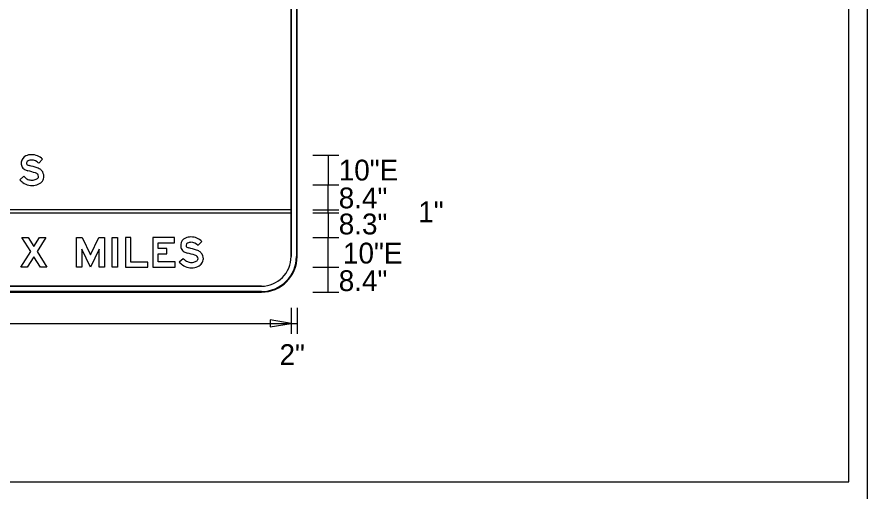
# Model space of a CAD drawing. Extents: x 17890484 to 17890754, y 17897495 to 17897992.
# Drawn here: x 17890540.84 to 17890564.64, y 17897572.31 to 17897585.59 of the extents above; entities that cross this region are included whole.
import ezdxf

# ---------------------------------------------------------------- set-up
doc = ezdxf.new("R2010")
doc.units = 0
for name, color, linetype in [('GSBWFill', 7, 'Continuous'), ('GSColorFill', 7, 'Continuous'), ('GSDims', 7, 'Continuous'), ('GSOutline', 7, 'Continuous'), ('SheetLinesMisc2_dp', 7, 'Continuous')]:
    doc.layers.add(name, color=color, linetype=linetype)

msp = doc.modelspace()

# ---------------------------------------------------------------- linework, layer by layer
at = {"layer": 'GSBWFill'}
for p, q in [((17890548.517, 17897590.883), (17890548.517, 17897578.883)), ((17890548.683, 17897578.883), (17890548.683, 17897590.883)), ((17890548.517, 17897580.186), (17890528.85, 17897580.186)), ((17890528.85, 17897580.103), (17890548.517, 17897580.103)), ((17890548.517, 17897580.103), (17890548.517, 17897580.186)), ((17890547.683, 17897578.049), (17890529.685, 17897578.049)), ((17890529.685, 17897577.883), (17890547.683, 17897577.883))]:
    msp.add_line(p, q, dxfattribs=at)
for points in [[(17890541.555, 17897581.605), (17890541.448, 17897581.5)], [(17890540.918, 17897581.034), (17890541.032, 17897581.132)], [(17890546.021, 17897579.3), (17890545.913, 17897579.195)], [(17890545.384, 17897578.729), (17890545.497, 17897578.827)]]:
    msp.add_lwpolyline(points, dxfattribs=at)
for points in [[(17890541.498, 17897578.582), (17890541.313, 17897578.877), (17890541.128, 17897578.582), (17890540.951, 17897578.582), (17890541.224, 17897579.018), (17890540.976, 17897579.415), (17890541.153, 17897579.415), (17890541.313, 17897579.159), (17890541.473, 17897579.415), (17890541.651, 17897579.415), (17890541.402, 17897579.018), (17890541.676, 17897578.582)], [(17890542.901, 17897578.931), (17890543.131, 17897579.415), (17890543.292, 17897579.415), (17890543.292, 17897578.582), (17890543.142, 17897578.582), (17890543.142, 17897579.09), (17890542.901, 17897578.582), (17890542.659, 17897579.09), (17890542.659, 17897578.582), (17890542.509, 17897578.582), (17890542.509, 17897579.415), (17890542.67, 17897579.415)], [(17890543.509, 17897578.582), (17890543.509, 17897579.415), (17890543.659, 17897579.415), (17890543.659, 17897578.582)], [(17890544.501, 17897578.582), (17890544.501, 17897578.727), (17890544.026, 17897578.727), (17890544.026, 17897579.415), (17890543.876, 17897579.415), (17890543.876, 17897578.582)], [(17890545.267, 17897578.732), (17890544.792, 17897578.732), (17890544.792, 17897578.956), (17890545.038, 17897578.956), (17890545.038, 17897579.106), (17890544.792, 17897579.106), (17890544.792, 17897579.265), (17890545.255, 17897579.265), (17890545.255, 17897579.415), (17890544.642, 17897579.415), (17890544.642, 17897578.582), (17890545.267, 17897578.582)]]:
    msp.add_lwpolyline(points, close=True, dxfattribs=at)
for centre, radius, start, end in [((17890541.176, 17897581.501), 0.218, 113.3248, 174.1421), ((17890541.247, 17897581.336), 0.398, 90, 113.3248), ((17890541.176, 17897581.501), 0.0679, 113.3248, 174.1421), ((17890541.247, 17897581.336), 0.248, 90, 113.3248), ((17890541.247, 17897581.303), 0.431, 44.4342, 90), ((17890541.247, 17897581.303), 0.281, 44.4342, 90), ((17890541.196, 17897581.499), 0.238, 174.1421, 201.2247), ((17890541.148, 17897581.481), 0.186, 201.2247, 240.1812), ((17890541.234, 17897581.631), 0.359, 240.1812, 256.1067), ((17890541.196, 17897581.499), 0.0882, 174.1421, 201.2247), ((17890541.148, 17897581.481), 0.0363, 201.2247, 240.1812), ((17890541.234, 17897581.631), 0.209, 240.1812, 256.1067), ((17890540.212, 17897577.501), 4.045, 72.8961, 76.1067), ((17890541.284, 17897580.985), 0.4, 63.0108, 72.8961), ((17890541.365, 17897581.143), 0.222, 39.5561, 63.0108), ((17890541.358, 17897581.413), 0.43, 220.8202, 232.6492), ((17890541.237, 17897581.255), 0.231, 232.6492, 260.7349), ((17890540.212, 17897577.501), 3.895, 72.8961, 76.1067), ((17890541.274, 17897581.268), 0.245, 281.6446, 306.0677), ((17890541.284, 17897580.985), 0.25, 63.0108, 72.8961), ((17890541.365, 17897581.143), 0.0724, 39.5561, 63.0108), ((17890541.385, 17897581.115), 0.0563, 306.0677, 343.4972), ((17890541.344, 17897581.126), 0.0993, 0, 39.5561), ((17890541.35, 17897581.126), 0.0932, 343.4972, 0), ((17890541.385, 17897581.115), 0.206, 306.0677, 343.4972), ((17890541.344, 17897581.126), 0.249, 0, 39.5561), ((17890541.35, 17897581.126), 0.243, 343.4972, 0), ((17890541.358, 17897581.413), 0.58, 220.8202, 232.6492), ((17890541.237, 17897581.255), 0.381, 232.6492, 260.7349), ((17890541.262, 17897581.41), 0.538, 260.7349, 270), ((17890541.262, 17897581.41), 0.388, 260.7349, 270), ((17890541.262, 17897581.328), 0.306, 270, 281.6446), ((17890541.262, 17897581.328), 0.456, 270, 281.6446), ((17890541.274, 17897581.268), 0.395, 281.6446, 306.0677), ((17890547.683, 17897578.883), 1, 270, 0), ((17890547.683, 17897578.883), 0.833, 270, 0)]:
    msp.add_arc(centre, radius, start, end, dxfattribs=at)
for centre, major_axis, start_param, end_param in [((17890545.641, 17897579.197), (0, 0.218), 0.407095, 1.468557), ((17890545.713, 17897579.031), (0, 0.398), 0, 0.407095), ((17890545.713, 17897578.998), (0, 0.431), 5.487912, 6.283185), ((17890545.662, 17897579.195), (0, 0.238), 1.468557, 1.941238), ((17890545.662, 17897579.195), (0, 0.0882), 1.468557, 1.941238), ((17890545.641, 17897579.197), (0, 0.0679), 0.407095, 1.468557), ((17890545.613, 17897579.176), (0, 0.0363), 1.941238, 2.621157), ((17890545.713, 17897579.031), (0, 0.248), 0, 0.407095), ((17890545.713, 17897578.998), (0, 0.281), 5.487912, 6.283185), ((17890545.613, 17897579.176), (0, 0.186), 1.941238, 2.621157), ((17890545.699, 17897579.326), (0, 0.359), 2.621157, 2.899109), ((17890545.699, 17897579.326), (0, 0.209), 2.621157, 2.899109), ((17890544.678, 17897575.196), (0, 3.895), 5.984666, 6.040702), ((17890544.678, 17897575.196), (0, 4.045), 5.984666, 6.040702), ((17890545.75, 17897578.68), (0, 0.25), 5.812135, 5.984666), ((17890545.75, 17897578.68), (0, 0.4), 5.812135, 5.984666), ((17890545.83, 17897578.838), (0, 0.222), 5.402773, 5.812135), ((17890545.81, 17897578.821), (0, 0.249), 4.712389, 5.402773), ((17890545.823, 17897579.109), (0, 0.58), 2.283243, 2.489697), ((17890545.823, 17897579.109), (0, 0.43), 2.283243, 2.489697), ((17890545.702, 17897578.95), (0, 0.231), 2.489697, 2.979885), ((17890545.728, 17897579.105), (0, 0.388), 2.979885, 3.141593), ((17890545.728, 17897579.023), (0, 0.306), 3.141593, 3.34483), ((17890545.74, 17897578.963), (0, 0.245), 3.34483, 3.771092), ((17890545.83, 17897578.838), (0, 0.0724), 5.402773, 5.812135), ((17890545.851, 17897578.811), (0, 0.0563), 3.771092, 4.424361), ((17890545.81, 17897578.821), (0, 0.0993), 4.712389, 5.402773), ((17890545.816, 17897578.821), (0, 0.0932), 4.424361, 4.712389), ((17890545.851, 17897578.811), (0, 0.206), 3.771092, 4.424361), ((17890545.816, 17897578.821), (0, 0.243), 4.424361, 4.712389), ((17890545.702, 17897578.95), (0, 0.381), 2.489697, 2.979885), ((17890545.728, 17897579.105), (0, 0.538), 2.979885, 3.141593), ((17890545.728, 17897579.023), (0, 0.456), 3.141593, 3.34483), ((17890545.74, 17897578.963), (0, 0.395), 3.34483, 3.771092)]:
    msp.add_ellipse(centre, major_axis=major_axis, ratio=0.999994, start_param=start_param, end_param=end_param, dxfattribs=at)
at = {"layer": 'GSColorFill'}
for p, q in [((17890548.517, 17897590.883), (17890548.517, 17897578.883)), ((17890548.667, 17897590.883), (17890548.667, 17897578.883)), ((17890548.683, 17897578.883), (17890548.683, 17897590.883)), ((17890548.683, 17897578.883), (17890548.683, 17897590.883)), ((17890548.683, 17897578.883), (17890548.683, 17897590.883)), ((17890548.517, 17897580.186), (17890528.85, 17897580.186)), ((17890528.85, 17897580.103), (17890548.517, 17897580.103)), ((17890548.517, 17897580.103), (17890548.517, 17897580.186)), ((17890547.683, 17897578.049), (17890529.685, 17897578.049)), ((17890547.683, 17897577.899), (17890529.683, 17897577.899)), ((17890529.683, 17897577.883), (17890547.683, 17897577.883)), ((17890529.683, 17897577.883), (17890547.683, 17897577.883)), ((17890529.685, 17897577.883), (17890547.683, 17897577.883))]:
    msp.add_line(p, q, dxfattribs=at)
for points in [[(17890541.555, 17897581.605), (17890541.448, 17897581.5)], [(17890540.918, 17897581.034), (17890541.032, 17897581.132)], [(17890546.021, 17897579.3), (17890545.913, 17897579.195)], [(17890545.384, 17897578.729), (17890545.497, 17897578.827)]]:
    msp.add_lwpolyline(points, dxfattribs=at)
for points in [[(17890541.498, 17897578.582), (17890541.313, 17897578.877), (17890541.128, 17897578.582), (17890540.951, 17897578.582), (17890541.224, 17897579.018), (17890540.976, 17897579.415), (17890541.153, 17897579.415), (17890541.313, 17897579.159), (17890541.473, 17897579.415), (17890541.651, 17897579.415), (17890541.402, 17897579.018), (17890541.676, 17897578.582)], [(17890542.901, 17897578.931), (17890543.131, 17897579.415), (17890543.292, 17897579.415), (17890543.292, 17897578.582), (17890543.142, 17897578.582), (17890543.142, 17897579.09), (17890542.901, 17897578.582), (17890542.659, 17897579.09), (17890542.659, 17897578.582), (17890542.509, 17897578.582), (17890542.509, 17897579.415), (17890542.67, 17897579.415)], [(17890543.509, 17897578.582), (17890543.509, 17897579.415), (17890543.659, 17897579.415), (17890543.659, 17897578.582)], [(17890544.501, 17897578.582), (17890544.501, 17897578.727), (17890544.026, 17897578.727), (17890544.026, 17897579.415), (17890543.876, 17897579.415), (17890543.876, 17897578.582)], [(17890545.267, 17897578.732), (17890544.792, 17897578.732), (17890544.792, 17897578.956), (17890545.038, 17897578.956), (17890545.038, 17897579.106), (17890544.792, 17897579.106), (17890544.792, 17897579.265), (17890545.255, 17897579.265), (17890545.255, 17897579.415), (17890544.642, 17897579.415), (17890544.642, 17897578.582), (17890545.267, 17897578.582)]]:
    msp.add_lwpolyline(points, close=True, dxfattribs=at)
for centre, radius, start, end in [((17890541.176, 17897581.501), 0.218, 113.3248, 174.1421), ((17890541.247, 17897581.336), 0.398, 90, 113.3248), ((17890541.176, 17897581.501), 0.0679, 113.3248, 174.1421), ((17890541.247, 17897581.336), 0.248, 90, 113.3248), ((17890541.247, 17897581.303), 0.431, 44.4342, 90), ((17890541.247, 17897581.303), 0.281, 44.4342, 90), ((17890541.196, 17897581.499), 0.238, 174.1421, 201.2247), ((17890541.148, 17897581.481), 0.186, 201.2247, 240.1812), ((17890541.234, 17897581.631), 0.359, 240.1812, 256.1067), ((17890541.196, 17897581.499), 0.0882, 174.1421, 201.2247), ((17890541.148, 17897581.481), 0.0363, 201.2247, 240.1812), ((17890541.234, 17897581.631), 0.209, 240.1812, 256.1067), ((17890540.212, 17897577.501), 4.045, 72.8961, 76.1067), ((17890541.284, 17897580.985), 0.4, 63.0108, 72.8961), ((17890541.365, 17897581.143), 0.222, 39.5561, 63.0108), ((17890541.358, 17897581.413), 0.43, 220.8202, 232.6492), ((17890541.237, 17897581.255), 0.231, 232.6492, 260.7349), ((17890540.212, 17897577.501), 3.895, 72.8961, 76.1067), ((17890541.274, 17897581.268), 0.245, 281.6446, 306.0677), ((17890541.284, 17897580.985), 0.25, 63.0108, 72.8961), ((17890541.365, 17897581.143), 0.0724, 39.5561, 63.0108), ((17890541.385, 17897581.115), 0.0563, 306.0677, 343.4972), ((17890541.344, 17897581.126), 0.0993, 0, 39.5561), ((17890541.35, 17897581.126), 0.0932, 343.4972, 0), ((17890541.385, 17897581.115), 0.206, 306.0677, 343.4972), ((17890541.344, 17897581.126), 0.249, 0, 39.5561), ((17890541.35, 17897581.126), 0.243, 343.4972, 0), ((17890541.358, 17897581.413), 0.58, 220.8202, 232.6492), ((17890541.237, 17897581.255), 0.381, 232.6492, 260.7349), ((17890541.262, 17897581.41), 0.538, 260.7349, 270), ((17890541.262, 17897581.41), 0.388, 260.7349, 270), ((17890541.262, 17897581.328), 0.306, 270, 281.6446), ((17890541.262, 17897581.328), 0.456, 270, 281.6446), ((17890541.274, 17897581.268), 0.395, 281.6446, 306.0677), ((17890547.683, 17897578.883), 1, 270, 0), ((17890547.683, 17897578.883), 1, 270, 0), ((17890547.683, 17897578.883), 0.833, 270, 0), ((17890547.683, 17897578.883), 1, 270, 0), ((17890547.683, 17897578.883), 0.983, 270, 0)]:
    msp.add_arc(centre, radius, start, end, dxfattribs=at)
for centre, major_axis, start_param, end_param in [((17890545.641, 17897579.197), (0, 0.218), 0.407095, 1.468557), ((17890545.713, 17897579.031), (0, 0.398), 0, 0.407095), ((17890545.713, 17897578.998), (0, 0.431), 5.487912, 6.283185), ((17890545.662, 17897579.195), (0, 0.238), 1.468557, 1.941238), ((17890545.662, 17897579.195), (0, 0.0882), 1.468557, 1.941238), ((17890545.641, 17897579.197), (0, 0.0679), 0.407095, 1.468557), ((17890545.613, 17897579.176), (0, 0.0363), 1.941238, 2.621157), ((17890545.713, 17897579.031), (0, 0.248), 0, 0.407095), ((17890545.713, 17897578.998), (0, 0.281), 5.487912, 6.283185), ((17890545.613, 17897579.176), (0, 0.186), 1.941238, 2.621157), ((17890545.699, 17897579.326), (0, 0.359), 2.621157, 2.899109), ((17890545.699, 17897579.326), (0, 0.209), 2.621157, 2.899109), ((17890544.678, 17897575.196), (0, 3.895), 5.984666, 6.040702), ((17890544.678, 17897575.196), (0, 4.045), 5.984666, 6.040702), ((17890545.75, 17897578.68), (0, 0.25), 5.812135, 5.984666), ((17890545.75, 17897578.68), (0, 0.4), 5.812135, 5.984666), ((17890545.83, 17897578.838), (0, 0.222), 5.402773, 5.812135), ((17890545.81, 17897578.821), (0, 0.249), 4.712389, 5.402773), ((17890545.823, 17897579.109), (0, 0.58), 2.283243, 2.489697), ((17890545.823, 17897579.109), (0, 0.43), 2.283243, 2.489697), ((17890545.702, 17897578.95), (0, 0.231), 2.489697, 2.979885), ((17890545.728, 17897579.105), (0, 0.388), 2.979885, 3.141593), ((17890545.728, 17897579.023), (0, 0.306), 3.141593, 3.34483), ((17890545.74, 17897578.963), (0, 0.245), 3.34483, 3.771092), ((17890545.83, 17897578.838), (0, 0.0724), 5.402773, 5.812135), ((17890545.851, 17897578.811), (0, 0.0563), 3.771092, 4.424361), ((17890545.81, 17897578.821), (0, 0.0993), 4.712389, 5.402773), ((17890545.816, 17897578.821), (0, 0.0932), 4.424361, 4.712389), ((17890545.851, 17897578.811), (0, 0.206), 3.771092, 4.424361), ((17890545.816, 17897578.821), (0, 0.243), 4.424361, 4.712389), ((17890545.702, 17897578.95), (0, 0.381), 2.489697, 2.979885), ((17890545.728, 17897579.105), (0, 0.538), 2.979885, 3.141593), ((17890545.728, 17897579.023), (0, 0.456), 3.141593, 3.34483), ((17890545.74, 17897578.963), (0, 0.395), 3.34483, 3.771092)]:
    msp.add_ellipse(centre, major_axis=major_axis, ratio=0.999994, start_param=start_param, end_param=end_param, dxfattribs=at)
at = {"layer": 'GSDims'}
for p, q in [((17890549.121, 17897581.719), (17890549.85, 17897581.719)), ((17890549.121, 17897581.719), (17890549.85, 17897581.719)), ((17890549.558, 17897581.719), (17890549.558, 17897580.886)), ((17890549.121, 17897580.886), (17890549.85, 17897580.886)), ((17890549.121, 17897580.886), (17890549.85, 17897580.886)), ((17890549.558, 17897580.186), (17890549.558, 17897580.886)), ((17890549.121, 17897580.186), (17890549.85, 17897580.186)), ((17890549.121, 17897580.186), (17890549.85, 17897580.186)), ((17890549.121, 17897580.103), (17890549.85, 17897580.103)), ((17890549.121, 17897580.103), (17890549.85, 17897580.103)), ((17890549.558, 17897580.103), (17890549.558, 17897580.186)), ((17890549.558, 17897580.103), (17890549.558, 17897579.415)), ((17890549.121, 17897579.415), (17890549.85, 17897579.415)), ((17890549.558, 17897578.582), (17890549.558, 17897579.415)), ((17890549.121, 17897578.582), (17890549.85, 17897578.582)), ((17890549.558, 17897577.883), (17890549.558, 17897578.582)), ((17890549.121, 17897577.883), (17890549.85, 17897577.883)), ((17890548.517, 17897577.445), (17890548.517, 17897576.716)), ((17890548.517, 17897577.445), (17890548.517, 17897576.716)), ((17890548.683, 17897577.445), (17890548.683, 17897576.716)), ((17890528.85, 17897577.008), (17890548.517, 17897577.008)), ((17890548.517, 17897577.008), (17890548.683, 17897577.008))]:
    msp.add_line(p, q, dxfattribs=at)
msp.add_lwpolyline([(17890548.517, 17897577.008), (17890547.933, 17897577.105), (17890547.933, 17897576.91)], close=True, dxfattribs=at)
at = {"layer": 'GSOutline'}
for p, q in [((17890548.517, 17897578.883), (17890548.517, 17897590.883)), ((17890548.683, 17897578.883), (17890548.683, 17897590.883)), ((17890548.517, 17897580.186), (17890528.85, 17897580.186)), ((17890528.85, 17897580.103), (17890548.517, 17897580.103)), ((17890548.517, 17897580.103), (17890548.517, 17897580.186)), ((17890529.683, 17897578.049), (17890547.683, 17897578.049)), ((17890529.683, 17897577.883), (17890547.683, 17897577.883))]:
    msp.add_line(p, q, dxfattribs=at)
for points in [[(17890541.555, 17897581.605), (17890541.448, 17897581.5)], [(17890540.918, 17897581.034), (17890541.032, 17897581.132)], [(17890546.021, 17897579.3), (17890545.913, 17897579.195)], [(17890545.384, 17897578.729), (17890545.497, 17897578.827)]]:
    msp.add_lwpolyline(points, dxfattribs=at)
for points in [[(17890541.498, 17897578.582), (17890541.313, 17897578.877), (17890541.128, 17897578.582), (17890540.951, 17897578.582), (17890541.224, 17897579.018), (17890540.976, 17897579.415), (17890541.153, 17897579.415), (17890541.313, 17897579.159), (17890541.473, 17897579.415), (17890541.651, 17897579.415), (17890541.402, 17897579.018), (17890541.676, 17897578.582)], [(17890542.901, 17897578.931), (17890543.131, 17897579.415), (17890543.292, 17897579.415), (17890543.292, 17897578.582), (17890543.142, 17897578.582), (17890543.142, 17897579.09), (17890542.901, 17897578.582), (17890542.659, 17897579.09), (17890542.659, 17897578.582), (17890542.509, 17897578.582), (17890542.509, 17897579.415), (17890542.67, 17897579.415)], [(17890543.509, 17897578.582), (17890543.509, 17897579.415), (17890543.659, 17897579.415), (17890543.659, 17897578.582)], [(17890544.501, 17897578.582), (17890544.501, 17897578.727), (17890544.026, 17897578.727), (17890544.026, 17897579.415), (17890543.876, 17897579.415), (17890543.876, 17897578.582)], [(17890545.267, 17897578.732), (17890544.792, 17897578.732), (17890544.792, 17897578.956), (17890545.038, 17897578.956), (17890545.038, 17897579.106), (17890544.792, 17897579.106), (17890544.792, 17897579.265), (17890545.255, 17897579.265), (17890545.255, 17897579.415), (17890544.642, 17897579.415), (17890544.642, 17897578.582), (17890545.267, 17897578.582)]]:
    msp.add_lwpolyline(points, close=True, dxfattribs=at)
for centre, radius, start, end in [((17890541.176, 17897581.501), 0.218, 113.3248, 174.1421), ((17890541.247, 17897581.336), 0.398, 90, 113.3248), ((17890541.176, 17897581.501), 0.0679, 113.3248, 174.1421), ((17890541.247, 17897581.336), 0.248, 90, 113.3248), ((17890541.247, 17897581.303), 0.431, 44.4342, 90), ((17890541.247, 17897581.303), 0.281, 44.4342, 90), ((17890541.196, 17897581.499), 0.238, 174.1421, 201.2247), ((17890541.148, 17897581.481), 0.186, 201.2247, 240.1812), ((17890541.234, 17897581.631), 0.359, 240.1812, 256.1067), ((17890541.196, 17897581.499), 0.0882, 174.1421, 201.2247), ((17890541.148, 17897581.481), 0.0363, 201.2247, 240.1812), ((17890541.234, 17897581.631), 0.209, 240.1812, 256.1067), ((17890540.212, 17897577.501), 4.045, 72.8961, 76.1067), ((17890541.284, 17897580.985), 0.4, 63.0108, 72.8961), ((17890541.365, 17897581.143), 0.222, 39.5561, 63.0108), ((17890541.358, 17897581.413), 0.43, 220.8202, 232.6492), ((17890541.237, 17897581.255), 0.231, 232.6492, 260.7349), ((17890540.212, 17897577.501), 3.895, 72.8961, 76.1067), ((17890541.274, 17897581.268), 0.245, 281.6446, 306.0677), ((17890541.284, 17897580.985), 0.25, 63.0108, 72.8961), ((17890541.365, 17897581.143), 0.0724, 39.5561, 63.0108), ((17890541.385, 17897581.115), 0.0563, 306.0677, 343.4972), ((17890541.344, 17897581.126), 0.0993, 0, 39.5561), ((17890541.35, 17897581.126), 0.0932, 343.4972, 0), ((17890541.385, 17897581.115), 0.206, 306.0677, 343.4972), ((17890541.344, 17897581.126), 0.249, 0, 39.5561), ((17890541.35, 17897581.126), 0.243, 343.4972, 0), ((17890541.358, 17897581.413), 0.58, 220.8202, 232.6492), ((17890541.237, 17897581.255), 0.381, 232.6492, 260.7349), ((17890541.262, 17897581.41), 0.538, 260.7349, 270), ((17890541.262, 17897581.41), 0.388, 260.7349, 270), ((17890541.262, 17897581.328), 0.306, 270, 281.6446), ((17890541.262, 17897581.328), 0.456, 270, 281.6446), ((17890541.274, 17897581.268), 0.395, 281.6446, 306.0677), ((17890547.683, 17897578.883), 1, 270, 0), ((17890547.683, 17897578.883), 0.833, 270, 0)]:
    msp.add_arc(centre, radius, start, end, dxfattribs=at)
for centre, major_axis, start_param, end_param in [((17890545.641, 17897579.197), (0, 0.218), 0.407095, 1.468557), ((17890545.713, 17897579.031), (0, 0.398), 0, 0.407095), ((17890545.713, 17897578.998), (0, 0.431), 5.487912, 6.283185), ((17890545.662, 17897579.195), (0, 0.238), 1.468557, 1.941238), ((17890545.662, 17897579.195), (0, 0.0882), 1.468557, 1.941238), ((17890545.641, 17897579.197), (0, 0.0679), 0.407095, 1.468557), ((17890545.613, 17897579.176), (0, 0.0363), 1.941238, 2.621157), ((17890545.713, 17897579.031), (0, 0.248), 0, 0.407095), ((17890545.713, 17897578.998), (0, 0.281), 5.487912, 6.283185), ((17890545.613, 17897579.176), (0, 0.186), 1.941238, 2.621157), ((17890545.699, 17897579.326), (0, 0.359), 2.621157, 2.899109), ((17890545.699, 17897579.326), (0, 0.209), 2.621157, 2.899109), ((17890544.678, 17897575.196), (0, 3.895), 5.984666, 6.040702), ((17890544.678, 17897575.196), (0, 4.045), 5.984666, 6.040702), ((17890545.75, 17897578.68), (0, 0.25), 5.812135, 5.984666), ((17890545.75, 17897578.68), (0, 0.4), 5.812135, 5.984666), ((17890545.83, 17897578.838), (0, 0.222), 5.402773, 5.812135), ((17890545.81, 17897578.821), (0, 0.249), 4.712389, 5.402773), ((17890545.823, 17897579.109), (0, 0.58), 2.283243, 2.489697), ((17890545.823, 17897579.109), (0, 0.43), 2.283243, 2.489697), ((17890545.702, 17897578.95), (0, 0.231), 2.489697, 2.979885), ((17890545.728, 17897579.105), (0, 0.388), 2.979885, 3.141593), ((17890545.728, 17897579.023), (0, 0.306), 3.141593, 3.34483), ((17890545.74, 17897578.963), (0, 0.245), 3.34483, 3.771092), ((17890545.83, 17897578.838), (0, 0.0724), 5.402773, 5.812135), ((17890545.851, 17897578.811), (0, 0.0563), 3.771092, 4.424361), ((17890545.81, 17897578.821), (0, 0.0993), 4.712389, 5.402773), ((17890545.816, 17897578.821), (0, 0.0932), 4.424361, 4.712389), ((17890545.851, 17897578.811), (0, 0.206), 3.771092, 4.424361), ((17890545.816, 17897578.821), (0, 0.243), 4.424361, 4.712389), ((17890545.702, 17897578.95), (0, 0.381), 2.489697, 2.979885), ((17890545.728, 17897579.105), (0, 0.538), 2.979885, 3.141593), ((17890545.728, 17897579.023), (0, 0.456), 3.141593, 3.34483), ((17890545.74, 17897578.963), (0, 0.395), 3.34483, 3.771092)]:
    msp.add_ellipse(centre, major_axis=major_axis, ratio=0.999994, start_param=start_param, end_param=end_param, dxfattribs=at)
at = {"layer": 'SheetLinesMisc2_dp'}
for p, q in [((17890564.641, 17897597.808), (17890564.641, 17897504.15)), ((17890564.13, 17897572.57), (17890564.13, 17897597.496)), ((17890512.958, 17897572.57), (17890564.13, 17897572.57))]:
    msp.add_line(p, q, dxfattribs=at)

# ---------------------------------------------------------------- texts
at = {"layer": 'GSDims'}
for s, p in [('10"E', (17890549.85, 17897581.011)), ('8.4"', (17890549.85, 17897580.231)), ('1"', (17890552.076, 17897579.842)), ('8.3"', (17890549.85, 17897579.501)), ('10"E', (17890549.969, 17897578.686)), ('8.4"', (17890549.85, 17897577.914)), ('2"', (17890548.191, 17897575.841))]:
    msp.add_text(s, height=0.5833, dxfattribs=at).set_placement(p)

doc.saveas('drawing.dxf')
